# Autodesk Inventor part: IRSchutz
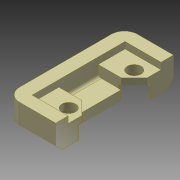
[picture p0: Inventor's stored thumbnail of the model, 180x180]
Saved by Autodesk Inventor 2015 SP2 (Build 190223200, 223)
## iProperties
Created: 2014-05
Part Number: IRSchutz
Material: Nylon 6/6
Document SubType Name: Modeling
Designer: AndreR
Density: 1.13 g/cm^3
Mass: 0.306333 g
Surface Area: 4.56525 cm^2
Volume: 0.271091 cm^3
Appearance: Nylon 6
Author: AndreR
Title: IRSchutz
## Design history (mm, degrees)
sketch "Skizze1"
  geometry: L1 (0, -9)-(7.5, -9); L2 (7.5, -9)-(7.5, -5); L3 (7.5, -5)-(5.5, -3); L4 (5.5, -3)-(5.5, 3); L5 (5.5, 3)-(7.5, 5); L6 (7.5, 5)-(7.5, 9); L7 (7.5, 9)-(0, 9); L8 (0, 9)-(0, -9); L9 (0, 12.6)-(0, -12.6) reference; L10 (-1.5, 0)-(9, 0) reference
  constraints: 16 end point, 3 parallel, 2 collinear, 2 perpendicular, 1 horizontal, 2 other
  dimensions: "d0" = 7.5 distance of L1.start L1.end; "d1" = 4 distance of L1.end L2.end; "d2" = 6 distance of L3.end L4.end; "d3" = 4 distance of L5.end L6.end; "d4" = 2 distance between parallel lines of L6 L4; "d5" = 2 horizontal distance of L4.end L5.end
extrude "Extrusion1" new body sketch "Skizze1" distance "d6" = 4; taper "d7" = 0 deg
sketch "Skizze2"
  geometry: L1 (0, -9)-(7.5, -9) reference; L2 (7.5, -9)-(7.5, -5) reference; L3 (7.5, -5)-(5.5, -3) reference; L4 (5.5, -3)-(5.5, 3) reference; L5 (5.5, 3)-(7.5, 5) reference; L6 (7.5, 5)-(7.5, 9) reference; L7 (7.5, 9)-(0, 9) reference; L8 (0, 9)-(0, -9) reference; L9 (5.5, 3)-(2, 3); L10 (2, 3)-(2, -3); L11 (2, -3)-(5.5, -3); L12 (5.5, -3)-(5.5, 3); 1 further point
  constraints: 8 end point, 2 parallel, 1 horizontal, 1 perpendicular, 1 point on line
  dimensions: "d8" = 3.5 distance of L11.end L10.end
extrude "Extrusion2" cut sketch "Skizze2" distance "d9" = 2.6; taper "d10" = 0 deg
sketch "Skizze3"
  geometry: L1 (2, 3)-(5.5, 3) reference; L2 (5.5, 3)-(7.5, 5) reference; L3 (7.5, 5)-(7.5, 9) reference; L4 (7.5, 9)-(0, 9) reference; L5 (0, 9)-(0, -9) reference; L6 (0, -9)-(7.5, -9) reference; L7 (7.5, -9)-(7.5, -5) reference; L8 (7.5, -5)-(5.5, -3) reference; L9 (5.5, -3)-(2, -3) reference; L10 (2, -3)-(2, 3) reference; L11 (7.5, -7.1)-(2, -7.1); L12 (2, 7.1)-(7.5, 7.1); L13 (7.5, 7.1)-(7.5, -7.1); L14 (-1.593, 0)-(9.559, 0) reference; L15 (7.5, 5)-(7.5, 9) reference; L16 (2, -7.1)-(2, 7.1); L17 (2, -3)-(2, 3) reference; 2 further points
  constraints: 8 end point, 2 collinear, 2 parallel, 1 point on line, 1 other
  dimensions: "d26" = 14.2 distance of L12.end L11.start
extrude "Extrusion3" cut sketch "Skizze3" distance "d13" = 1; taper "d14" = 0 deg
sketch "Skizze4"
  geometry: L1 (0, -9)-(-7.5, -9) reference; L2 (0, 9)-(0, -9) reference; L3 (-7.5, 9)-(0, 9) reference; L4 (-7.5, 5)-(-7.5, 9) reference; L5 (-5.5, 3)-(-7.5, 5) reference; L6 (-5.5, -3)-(-5.5, 3) reference; L7 (-7.5, -5)-(-5.5, -3) reference; L8 (-7.5, -9)-(-7.5, -5) reference; 3 further points
  dimensions: "d15" = 2 distance from line of L4 point (-5.5, 5); "d16" = 2 distance of point (-5.5, 5) L5.start; "d17" = 2 distance of point (-5.5, -5) L6.start; "d18" = 2 distance of point (-5.5, -5) L7.start
hole "Bohrung1" sketch "Skizze4" at (-5.5, 5), (-5.5, -5) diameter "d19" = 2.1; stored, may be unused: countersink angle "d23" = 90 deg, drill point angle "d25" = 118 deg; dims "d20" = 6, "d21" = 4.1, "d22" = 2, "d24" = 8
fillet "Rundung1" dims "d27" = 2
chamfer "Fase1" distance "d30" = 1; stored, may be unused: second distance "d31" = 2, angle "d32" = 45 deg
fillet "Rundung2" dims "d33" = 0.5
node "Volumenkörper1"
node "Projizierte Kontur1"
node "Projizierte Kontur2"
node "Projizierte Kontur3"
